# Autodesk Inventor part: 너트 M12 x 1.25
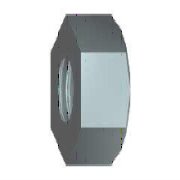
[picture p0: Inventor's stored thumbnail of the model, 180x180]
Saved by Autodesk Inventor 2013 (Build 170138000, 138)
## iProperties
IsCustomPart: 0
Created: 2015-12
Part Number: 너트 M12 x 1.25
Material: 스테인리스강
Description: 6각 너트
Document SubType Name: Modeling
Standard: KS B 1012
Designer: mdu
Standards Organization: KS
Language: ko-KR
Size Designation: M12x1.25
Categories: <MemberInstance><Categories><Category DisplayName="조임쇠" InternalName="e4da775c-781d-43d5-af7c-5136215cf5a6" Mnemonic="FSTN"><Category DisplayName="너트" InternalN
Density: 8.08 g/cm^3
Author: mdu
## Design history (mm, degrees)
sketch "스케치1"
  geometry: L1 (10.97, 0)-(5.485, -9.5); L2 (5.485, -9.5)-(-5.485, -9.5); L3 (-5.485, -9.5)-(-10.97, 0); L4 (-10.97, 0)-(-5.485, 9.5); L5 (-5.485, 9.5)-(5.485, 9.5); L6 (5.485, 9.5)-(10.97, 0); 2 further points
  constraints: 12 end point, 1 coincident, 1 horizontal, 11 other
  dimensions: "d0" = 21.93931 distance of L1.start L3.end (= 1.1547 x SW)
extrude "본체" new body sketch "스케치1" distance "d1" = 10 (= KOH); taper "d2" = 0 deg
sketch "스케치2"
  geometry: 1 further point
hole "스레드" sketch "스케치2" diameter "d6" = 10.647; stored, may be unused: countersink angle "d10" = 82 deg, drill point angle "d12" = 118 deg; dims "d7" = 12.7, "d8" = 9.525, "d9" = 6.35, "d11" = 19.05
sketch "스케치3"
  geometry: L1 (0, 10.97)-(10, 10.97) reference; L2 (10, 5.485)-(10, 10.97) reference; L3 (-2, 0)-(12, 0) reference; L4 (9.151, 10.97)-(10, 9.5)
  constraints: 2 end point, 2 point on line
  dimensions: "d3" = 19 diameter of L4.end L3 (= SW01); "d4" = 30 deg angle of L2 L4 (= ANG2)
revolve "모따기3" sketch "스케치3" stored, may be unused: angle "d5" = 90 deg
workaxis "Work Axis1"
workplane "Work Plane1"
body "Solid1"
chamfer "모따기1" distance "d13" = 0.67658 (= -0.5 x GD1 + 0.5 x NND); stored, may be unused: angle "d14" = 30 deg, second distance "d21" = 0.67658 (= -0.5 x GD1 + 0.5 x NND)
chamfer "모따기2" distance "d15" = 0.67658 (= -0.5 x GD1 + 0.5 x NND); stored, may be unused: angle "d16" = 30 deg, second distance "d22" = 0.67658 (= -0.5 x GD1 + 0.5 x NND)
other parameters: "ANG2" = 30 deg [user parameter; used in 1 equation term], "NND" = 12 [user parameter; used in 4 equation terms], "KOH" = 10 [user parameter; used in 1 equation term], "SW" = 19 [user parameter; used in 3 equation terms], "SW01" = 19 (= SW) [user parameter; used in 1 equation term], "GD1" = 10.64684 (computed from THREADDIA, PTC, TOA) [user parameter; used in 4 equation terms], "d19" = 0, "d20" = 0, "d24" = 0, "d25" = 0, "GUL" = 0.67658 (= 0.541266 x PTC) [user parameter], "TPU" = 8 (computed from PTC) [user parameter], "TOA" = 30 deg [user parameter; used in 1 equation term], "PTC" = 1.25 [user parameter; used in 4 equation terms], "E0" = 21.945 (= 1.155 x SW) [user parameter], "THREADDIA" = 12 [user parameter; used in 1 equation term], "GAL" = 0.67658 (= 0.541266 x PTC) [user parameter]
